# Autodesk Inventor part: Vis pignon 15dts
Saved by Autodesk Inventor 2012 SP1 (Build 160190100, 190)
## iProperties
Created: 2014-12
Part Number: Vis pignon 15dts
Material: Default
Document SubType Name: Modeling
Designer: Bruno
Density: 1 g/cm^3
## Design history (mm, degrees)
node "Vis pignon 15dts1"
node "Vis pignon 15dts"
node "Base1"
